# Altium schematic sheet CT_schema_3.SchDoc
size 218 x 258 mm
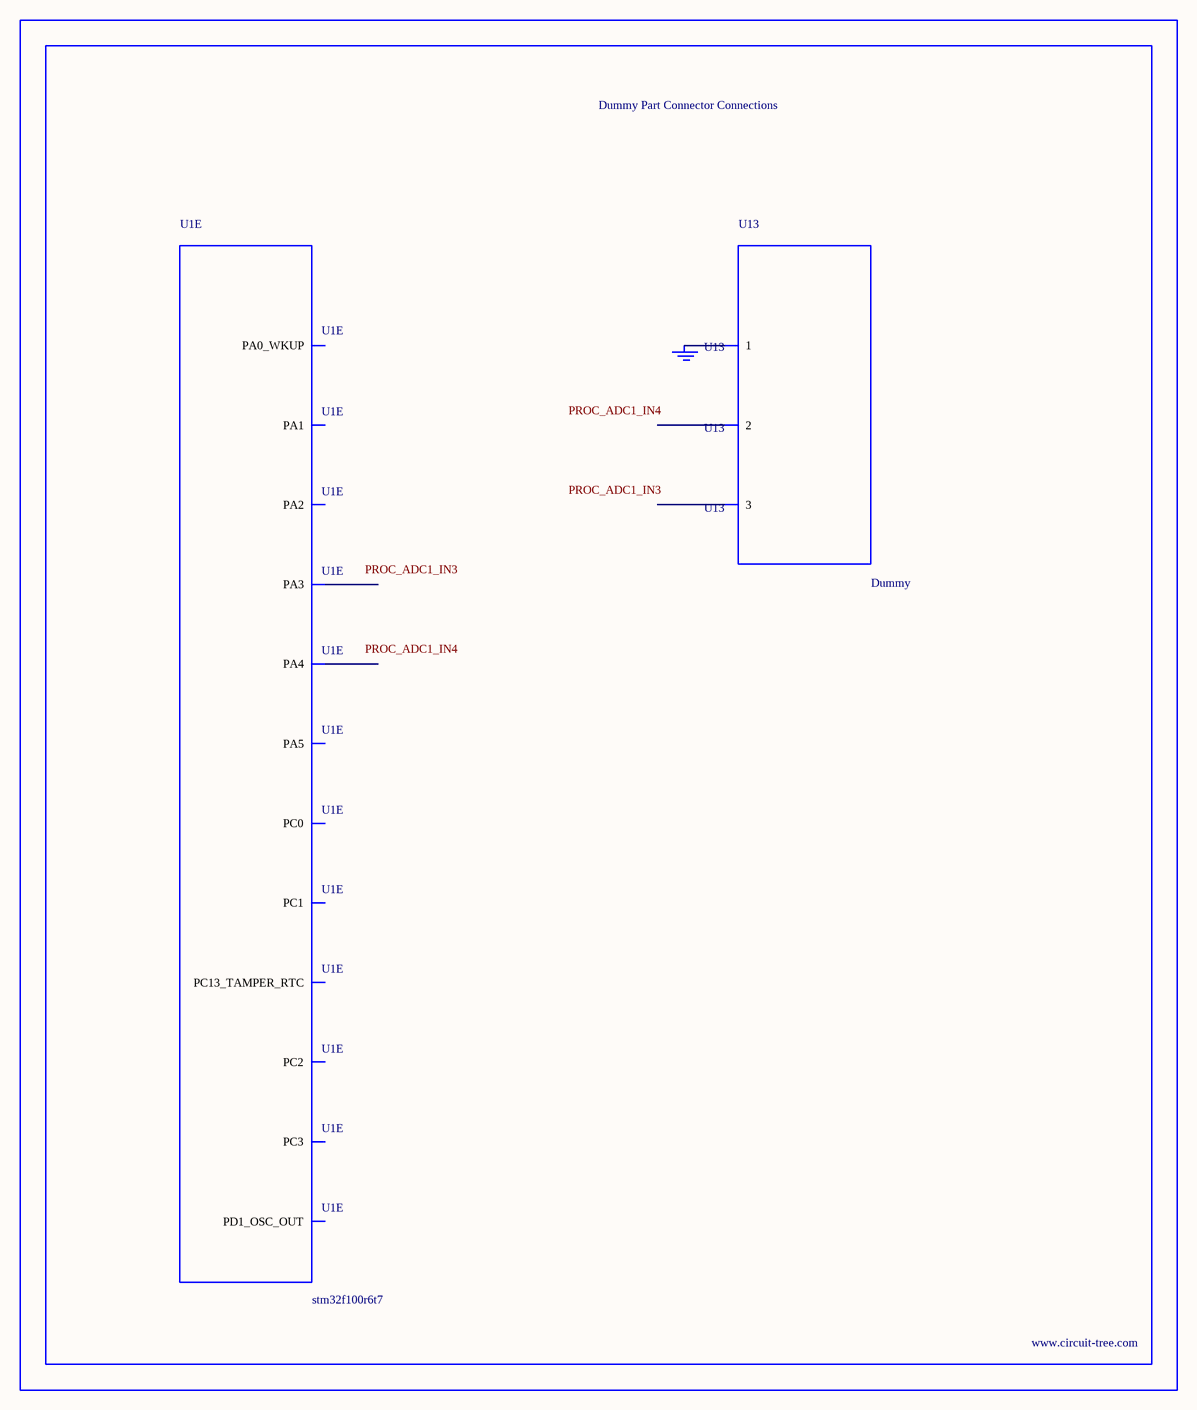
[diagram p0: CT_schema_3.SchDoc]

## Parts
BORDER2  (no value)
GND_INSTANCE_2_0  (no value)
U1  stm32f100r6t7  [LQFP64]  (part E of 5)
U13  Dummy  [DUMMY_PACKAGE_109]

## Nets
NetGND_INSTANCE_2_0_0: GND_INSTANCE_2_0.0(GND) U13.1

Not connected (* = marked no-connect by the designer): U1 2(PC13_TAMPER_RTC) 6(PD1_OSC_OUT) 8(PC0) 9(PC1) 10(PC2) 11(PC3) 14(PA0_WKUP) 15(PA1) 16(PA2) 17(PA3) 20(PA4) 21(PA5); U13 2 3

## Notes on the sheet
- Labels drawn without touching a wire or pin: PROC_ADC1_IN3, PROC_ADC1_IN4

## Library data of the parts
BORDER2 = BORDER_PAGE2
GND_INSTANCE_2_0 = GND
